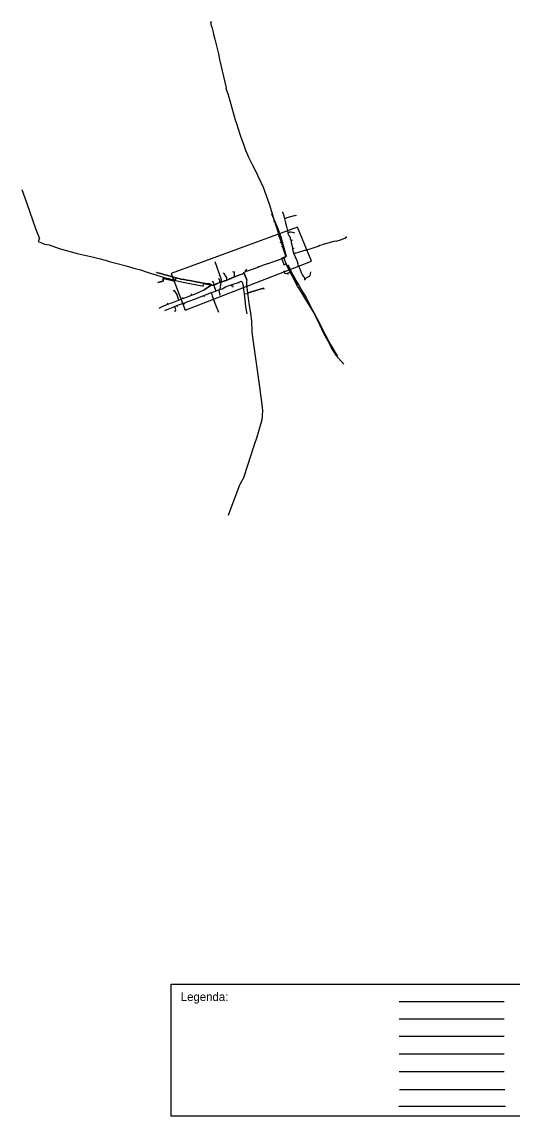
# Model space of a CAD drawing. Extents: x -703329 to -700959, y -1023502 to -1021532.
# Drawn here: x -703329 to -702465, y -1023458 to -1021532 of the extents above; entities that cross this region are included whole.
import ezdxf

# ---------------------------------------------------------------- set-up
doc = ezdxf.new("R2010")
doc.units = 0
for name, color, linetype in [('Vrstva 1', 7, 'Continuous'), ('Vrstva 2', 7, 'Continuous'), ('Vrstva 4', 7, 'Continuous'), ('Vrstva 63', 7, 'Continuous')]:
    doc.layers.add(name, color=color, linetype=linetype)

msp = doc.modelspace()

# ---------------------------------------------------------------- linework, layer by layer
at = {"layer": 'Vrstva 1'}
for p, q in [((-702664.172464, -1023255.776886), (-702478.762828, -1023255.776886)), ((-702664.172464, -1023286.503889), (-702478.762828, -1023286.503889)), ((-702664.172464, -1023317.230892), (-702478.762828, -1023317.230892)), ((-702664.172464, -1023347.957894), (-702478.762828, -1023347.957894)), ((-702664.172464, -1023379.35302), (-702478.762828, -1023379.35302)), ((-702663.25266, -1023410.831495), (-702477.843025, -1023410.831495)), ((-702664.422703, -1023440.270888), (-702476.414852, -1023440.270888))]:
    msp.add_line(p, q, dxfattribs=at)
for points in [[(-703328.627, -1021827.093), (-703320.441, -1021849.961), (-703303.784, -1021897.106), (-703297.781, -1021912.82), (-703298.038, -1021913.443), (-703299.559, -1021917.143), (-703300.128, -1021918.527), (-703293.861, -1021920.979), (-703288.734, -1021923.253), (-703280.419, -1021924.122), (-703262.932, -1021930.461), (-703231.327, -1021939.317), (-703217.484, -1021942.7), (-703204.749, -1021945.514), (-703190.729, -1021948.878), (-703178.041, -1021952.517), (-703172.493, -1021954.057), (-703163.326, -1021956.477), (-703145.017, -1021961.356), (-703131.4, -1021965.203), (-703119.891, -1021968.321), (-703107.62, -1021972.273), (-703083.486, -1021979.941), (-703077.893, -1021981.448), (-703070.423, -1021983.514), (-703057.214, -1021987.099), (-703044.292, -1021990.048), (-703032.48, -1021992.498), (-703020.324, -1021994.812), (-703011.714, -1021996.489)], [(-702889.616, -1021864.148), (-702887.85, -1021869.34), (-702886.67, -1021873.56), (-702883.87, -1021881.93), (-702883.51, -1021882.8)], [(-702869.594, -1021866.237), (-702869.46, -1021866.94), (-702867.93, -1021870.72), (-702865.76, -1021878.41)], [(-702867.93, -1021870.72), (-702865.76, -1021878.41)], [(-702865.76, -1021878.41), (-702864.035, -1021876.989), (-702857.367, -1021874.767), (-702845.672, -1021871.95), (-702845.402, -1021872.92)], [(-702865.76, -1021878.41), (-702864.05, -1021885.73)], [(-702884.788, -1021883.229), (-702883.51, -1021882.8)], [(-702883.51, -1021882.8), (-702881.58, -1021889.28), (-702879.86, -1021891.99), (-702879.44, -1021894.19), (-702878.88, -1021894.84), (-702875.17, -1021909.07)], [(-702864.05, -1021885.73), (-702862.52, -1021892.07), (-702861.44, -1021896.39), (-702860.84, -1021899.05), (-702859.81, -1021903.45)], [(-702862.52, -1021892.07), (-702861.44, -1021896.39)], [(-702876.092, -1021909.185), (-702875.17, -1021909.07)], [(-702875.17, -1021909.07), (-702873.9, -1021912.79), (-702872.05, -1021918.22), (-702871.51, -1021919.79), (-702870.54, -1021922.95), (-702869.2, -1021926.63)], [(-702873.9, -1021912.79), (-702872.05, -1021918.22)], [(-702860.84, -1021899.05), (-702859.81, -1021903.45)], [(-702859.81, -1021903.45), (-702857.14, -1021901.17), (-702855.53, -1021901.27), (-702851.63, -1021901.86), (-702848.458, -1021903.244)], [(-702859.81, -1021903.45), (-702859.23, -1021905.91), (-702857.45, -1021907.91), (-702856.11, -1021911.76), (-702855.91, -1021912.88), (-702854.81, -1021915.89), (-702854.698, -1021916.268)], [(-702855.91, -1021912.88), (-702854.81, -1021915.89)], [(-702854.698, -1021916.268), (-702852.809, -1021915.714), (-702851.882, -1021916.067)], [(-702854.698, -1021916.268), (-702854.12, -1021918.22), (-702854.05, -1021920.37), (-702852.12, -1021928.93), (-702851.89, -1021930.35), (-702851.833, -1021930.771)], [(-702847.95, -1021938.38), (-702846.71, -1021938.87), (-702845.83, -1021938.78), (-702842.95, -1021937.97), (-702830.28, -1021933.63), (-702828.21, -1021933.32), (-702816.91, -1021929.8), (-702806.89, -1021926.56), (-702803.66, -1021925.01), (-702798.55, -1021923.45), (-702797.52, -1021922.81), (-702795.07, -1021922.53), (-702776.56, -1021916.99), (-702774.96, -1021917.56), (-702767.18, -1021915.43), (-702759.63, -1021912.62), (-702756.7, -1021910.71), (-702756.48, -1021910.63), (-702756.757, -1021909.7)], [(-702912.33, -1021963.25), (-702911.91, -1021963.18), (-702902.23, -1021959.63), (-702898.93, -1021958.48), (-702897.04, -1021957.85), (-702895.96, -1021957.02), (-702894.48, -1021956.96), (-702878, -1021951.21), (-702864.71, -1021946.48), (-702863.57, -1021944.43), (-702866.29, -1021935.52)], [(-702871.51, -1021919.79), (-702870.54, -1021922.95)], [(-702870.509, -1021927.043), (-702869.2, -1021926.63)], [(-702866.29, -1021935.52), (-702867.17, -1021933.46), (-702868.09, -1021930.25), (-702869.2, -1021926.63)], [(-702868.09, -1021930.25), (-702867.17, -1021933.46)], [(-702851.833, -1021930.771), (-702848.639, -1021929.836)], [(-702851.833, -1021930.771), (-702851.6, -1021932.5), (-702850.04, -1021938.06)], [(-702850.04, -1021938.06), (-702849.52, -1021940.34), (-702845.04, -1021950.46), (-702844.19, -1021952.06), (-702842.4, -1021956.31), (-702843.26, -1021958.53), (-702842.59, -1021960.15), (-702841.93, -1021960.76)], [(-702850.04, -1021938.06), (-702847.95, -1021938.38)], [(-702849.52, -1021940.34), (-702845.04, -1021950.46)], [(-703090.69, -1021972.86), (-703090.44, -1021971.93)], [(-703076.98, -1021976.95), (-703084.06, -1021974.89), (-703089.77, -1021973.23), (-703090.69, -1021972.86)], [(-703090.69, -1021972.86), (-703089.77, -1021973.23), (-703084.06, -1021974.89), (-703076.98, -1021976.95)], [(-702973.715, -1021973.823), (-702972.591, -1021973.404), (-702970.446, -1021978.581), (-702968.39, -1021981.65), (-702968.23, -1021986.31)], [(-702948.291, -1021978.321), (-702937.184, -1021974.246), (-702936.546, -1021975.842), (-702932.464, -1021986.056), (-702933.07, -1021988.955), (-702932.663, -1021994.753), (-702928.736, -1022027.563), (-702925.495, -1022047.954), (-702924.396, -1022054.867), (-702924.106, -1022056.693), (-702923.266, -1022078.142), (-702916.795, -1022124.218), (-702910.182, -1022174.299), (-702905.394, -1022210.194), (-702904.438, -1022216.613), (-702906.141, -1022231.995), (-702914.848, -1022262.842), (-702919.275, -1022276.127), (-702920.535, -1022280.161), (-702921.603, -1022283.279), (-702925.395, -1022294.352), (-702937.779, -1022332.503), (-702938.28, -1022334.101), (-702938.76, -1022335.369), (-702943.944, -1022344.666), (-702945.34, -1022347.169), (-702960.655, -1022387.911), (-702965.12, -1022400.867)], [(-702956.654, -1021971.555), (-702955.577, -1021971.153), (-702954.761, -1021973.196), (-702954.77, -1021976.35), (-702954.69, -1021978.46), (-702955.23, -1021980.78)], [(-702955.23, -1021980.78), (-702949.74, -1021978.62), (-702945.56, -1021976.96), (-702939.41, -1021974.98), (-702937.64, -1021973.66), (-702937.4, -1021972.45), (-702937.34, -1021972.17), (-702935.43, -1021971.59), (-702934.122, -1021971.079)], [(-702934.122, -1021971.079), (-702935.43, -1021971.59)], [(-702934.122, -1021971.079), (-702934.759, -1021969.451), (-702932.537, -1021967.058)], [(-702934.122, -1021971.079), (-702932.82, -1021970.57), (-702925.85, -1021968.07), (-702922.57, -1021966.97), (-702920.52, -1021966.23), (-702912.33, -1021963.25)], [(-702932.82, -1021970.57), (-702934.122, -1021971.079)], [(-702922.57, -1021966.97), (-702920.52, -1021966.23)], [(-702912.94, -1021961.69), (-702912.33, -1021963.25)], [(-702902.23, -1021959.63), (-702898.93, -1021958.48)], [(-702867.452, -1021970.064), (-702866.729, -1021972.014), (-702865.69, -1021974.2), (-702864.11, -1021974.47), (-702860.69, -1021974.07)], [(-702860.69, -1021974.07), (-702855.76, -1021972.12)], [(-702860.69, -1021974.07), (-702860.309, -1021976.568)], [(-702855.76, -1021972.12), (-702845.19, -1021992.54), (-702843.24, -1021995.4)], [(-702841.93, -1021960.76), (-702841.17, -1021960.65)], [(-702841.93, -1021960.76), (-702840.2, -1021964.06)], [(-702841.93, -1021960.76), (-702840.2, -1021964.06), (-702838.47, -1021967.83), (-702836.52, -1021972.81), (-702834.07, -1021977.71), (-702832.79, -1021979.12), (-702831.51, -1021981.3), (-702830.44, -1021984.37)], [(-702830.44, -1021984.37), (-702828.95, -1021983.39), (-702827.84, -1021982.37), (-702820.822, -1021978.535), (-702819.657, -1021971.569)], [(-703079.52, -1021983.09), (-703079.39, -1021988.13), (-703086.78, -1021989.85), (-703089.16, -1021990.71)], [(-703057.096, -1021982.303), (-703057.44, -1021983.57), (-703059.04, -1021986.63), (-703059.58, -1021987.88), (-703060.14, -1021988.12), (-703062.99, -1021987.22), (-703076.5, -1021983.85), (-703079.52, -1021983.09)], [(-703076.98, -1021976.95), (-703076.68, -1021976.09)], [(-703065.426, -1021980.075), (-703071.31, -1021978.38), (-703076.98, -1021976.95)], [(-703076.98, -1021976.95), (-703071.31, -1021978.38), (-703065.426, -1021980.075)], [(-703065.426, -1021980.075), (-703065.256, -1021979.484)], [(-703057.096, -1021982.303), (-703059.12, -1021981.8), (-703062.98, -1021980.78), (-703065.426, -1021980.075)], [(-703065.426, -1021980.075), (-703062.98, -1021980.78), (-703059.12, -1021981.8), (-703057.096, -1021982.303)], [(-703062.99, -1021987.22), (-703060.14, -1021988.12), (-703059.58, -1021987.88), (-703059.04, -1021986.63), (-703057.44, -1021983.57), (-703057.096, -1021982.303)], [(-703056.829, -1021982.399), (-703057.096, -1021982.303)], [(-703057.096, -1021982.303), (-703056.829, -1021982.399)], [(-703056.829, -1021982.399), (-703056.79, -1021982.248)], [(-703054.854, -1021982.954), (-703056.829, -1021982.399)], [(-703056.829, -1021982.399), (-703054.854, -1021982.954)], [(-703049.595, -1021984.29), (-703054.854, -1021982.954)], [(-703054.854, -1021982.954), (-703049.595, -1021984.29)], [(-703049.595, -1021984.29), (-703049.374, -1021983.441)], [(-703039.37, -1021986.033), (-703043.42, -1021985.354), (-703049.14, -1021984.41), (-703049.595, -1021984.29)], [(-703049.595, -1021984.29), (-703049.14, -1021984.41), (-703043.42, -1021985.354), (-703039.37, -1021986.033)], [(-703039.37, -1021986.033), (-703039.243, -1021985.282)], [(-703029.535, -1021987.861), (-703033.112, -1021987.238), (-703038.382, -1021986.211), (-703039.37, -1021986.033)], [(-703039.37, -1021986.033), (-703038.382, -1021986.211), (-703033.112, -1021987.238), (-703029.535, -1021987.861)], [(-703029.57, -1022012.86), (-703021.4, -1022009.59), (-703007.3, -1022003.38), (-702995.36, -1021994.95), (-702993.48, -1021995.03)], [(-703029.535, -1021987.861), (-703029.404, -1021987.051)], [(-703029.535, -1021987.861), (-703024.682, -1021988.666), (-703020.708, -1021989.357), (-703015.28, -1021990.357)], [(-703015.28, -1021990.357), (-703020.708, -1021989.357), (-703024.682, -1021988.666), (-703029.535, -1021987.861)], [(-703015.28, -1021990.357), (-703015.138, -1021989.621)], [(-703015.28, -1021990.357), (-703012.37, -1021990.921), (-703008.422, -1021991.691), (-703001.49, -1021992.96), (-702997.57, -1021992.81), (-702993.48, -1021995.03)], [(-702993.48, -1021995.03), (-702997.57, -1021992.81), (-703001.49, -1021992.96), (-703008.422, -1021991.691), (-703012.37, -1021990.921), (-703015.28, -1021990.357)], [(-703011.027, -1021996.623), (-703009.263, -1021996.966), (-703007.79, -1021992.364), (-703006.323, -1021992.638)], [(-702995.36, -1021994.95), (-703007.3, -1022003.38)], [(-703006.323, -1021992.638), (-703005.537, -1021992.785)], [(-703005.537, -1021992.785), (-702996.942, -1021994.391), (-702991.596, -1021995.211), (-702986.613, -1021993.062)], [(-702993.48, -1021995.03), (-702992.91, -1021995.16), (-702992.34, -1021994.96)], [(-702993.28, -1021987.888), (-702991.46, -1021990.58), (-702990.34, -1021994.97)], [(-702992.34, -1021994.96), (-702990.71, -1021995.01)], [(-702990.71, -1021995.01), (-702990.34, -1021994.97)], [(-702990.34, -1021994.97), (-702987.613, -1021993.592), (-702986.84, -1021993.19), (-702983.98, -1021991.88), (-702980.542, -1021990.57)], [(-702990.34, -1021994.97), (-702987.613, -1021993.592), (-702986.84, -1021993.19)], [(-702986.613, -1021993.062), (-702985.408, -1021992.543), (-702980.036, -1021990.512), (-702974.43, -1021988.604), (-702968.893, -1021986.753), (-702960.411, -1021983.749), (-702955.208, -1021981.166), (-702952.324, -1021979.801)], [(-702982.458, -1021984.104), (-702981.476, -1021983.733), (-702980.473, -1021986.39), (-702980.542, -1021990.57)], [(-702980.542, -1021990.57), (-702976.39, -1021988.99), (-702973.16, -1021987.99), (-702970.83, -1021987.17)], [(-702970.83, -1021987.17), (-702968.23, -1021986.31)], [(-702968.23, -1021986.31), (-702966.33, -1021985.61), (-702962.95, -1021984.1), (-702962.62, -1021983.76)], [(-702968.23, -1021986.31), (-702966.33, -1021985.61), (-702962.95, -1021984.1)], [(-702963.51, -1021996.08), (-702960.12, -1021994.67)], [(-702962.62, -1021983.76), (-702961.796, -1021983.428)], [(-702961.796, -1021983.428), (-702955.23, -1021980.78)], [(-702961.796, -1021983.428), (-702961.19, -1021984.93)], [(-702960.12, -1021994.67), (-702956.07, -1021993.54), (-702947.22, -1021990.29)], [(-702960.12, -1021994.67), (-702959.45, -1021996.32), (-702957.791, -1021995.709), (-702956.725, -1021998.591)], [(-702955.23, -1021980.78), (-702949.74, -1021978.62)], [(-702952.324, -1021979.801), (-702948.291, -1021978.321)], [(-702947.22, -1021990.29), (-702942, -1021988.35), (-702941.13, -1021989.14), (-702940.77, -1021990.19), (-702939.01, -1021995.89), (-702938.86, -1021997.73), (-702937.98, -1022003.39), (-702937.059, -1022010.427)], [(-702947.22, -1021990.29), (-702946.716, -1021991.562)], [(-702932.464, -1021986.056), (-702936.546, -1021975.842)], [(-702831.51, -1021981.3), (-702830.44, -1021984.37)], [(-702830.44, -1021984.37), (-702829.22, -1021986.54)], [(-703062.355, -1022004.654), (-703060.038, -1022004.594), (-703058.796, -1022007.739), (-703055.86, -1022011.516), (-703055.571, -1022012.315), (-703054.293, -1022016), (-703052.6, -1022020.94), (-703052.53, -1022021.64)], [(-703045.07, -1022018.9), (-703036.63, -1022015.53), (-703029.57, -1022012.86)], [(-703043.294, -1022026.675), (-703039.68, -1022025.52), (-703036.28, -1022023.76), (-703022.66, -1022019.03), (-703009.66, -1022013.84), (-703006.964, -1022012.752)], [(-703030.576, -1022010.701), (-703029.57, -1022012.86)], [(-703011.714, -1021996.489), (-703011.027, -1021996.623)], [(-703007.387, -1022015.356), (-703007.623, -1022014.461), (-703006.459, -1022014.005), (-703006.964, -1022012.752)], [(-703006.964, -1022012.752), (-703003.59, -1022011.39), (-702994.97, -1022008.06)], [(-702994.97, -1022008.06), (-702987.2, -1022005.48)], [(-702994.97, -1022008.06), (-702994.46, -1022009.57), (-702993.59, -1022013.95), (-702990.69, -1022021.95), (-702987.43, -1022029.77), (-702982.014, -1022042.747)], [(-702990.71, -1021995.01), (-702990.05, -1021997.78), (-702987.65, -1022003.98), (-702987.2, -1022005.48)], [(-702990.05, -1021997.78), (-702987.65, -1022003.98)], [(-702987.2, -1022005.48), (-702985.42, -1022004.86), (-702982.23, -1022003.71)], [(-702982.23, -1022003.71), (-702980.06, -1022002.73), (-702978.15, -1022002.27), (-702977.412, -1022002.03)], [(-702982.23, -1022003.71), (-702981.84, -1022004.85), (-702979.648, -1022012.612), (-702980.584, -1022012.964)], [(-702977.61, -1022001.42), (-702977.412, -1022002.03)], [(-702977.412, -1022002.03), (-702975.57, -1022001.43)], [(-702975.57, -1022001.43), (-702970.09, -1021998.26), (-702963.51, -1021996.08)], [(-702938.86, -1021997.73), (-702937.98, -1022003.39)], [(-702937.059, -1022010.427), (-702935.693, -1022010.271), (-702931.202, -1022009.757), (-702929.635, -1022009.578)], [(-702937.059, -1022010.427), (-702935.7, -1022020.81), (-702934.36, -1022033.51), (-702932.55, -1022045.5)], [(-702935.693, -1022010.271), (-702931.202, -1022009.757)], [(-702902.341, -1022002.418), (-702903.167, -1022000.265), (-702929.719, -1022008.771), (-702929.635, -1022009.578)], [(-702929.635, -1022009.578), (-702929.719, -1022008.771), (-702903.167, -1022000.265), (-702902.341, -1022002.418)], [(-703086.51, -1022035.8), (-703081.39, -1022033.01), (-703071.41, -1022028.85)], [(-703076.69, -1022039.84), (-703069.62, -1022036.78), (-703063.92, -1022034.68), (-703059.22, -1022032.75)], [(-703072.358, -1022026.159), (-703071.41, -1022028.85)], [(-703071.41, -1022028.85), (-703061.38, -1022025.05), (-703052.53, -1022021.64)], [(-703059.486, -1022041.225), (-703057.68, -1022040.41), (-703057.58, -1022038.66), (-703058.69, -1022034.31), (-703059.22, -1022032.75)], [(-703059.22, -1022032.75), (-703055.59, -1022030.96)], [(-703055.59, -1022030.96), (-703049.31, -1022028.51), (-703045.87, -1022027.5), (-703044.68, -1022027.16), (-703043.294, -1022026.675)], [(-703055.59, -1022030.96), (-703054.912, -1022032.878)], [(-703052.53, -1022021.64), (-703045.07, -1022018.9)], [(-703045.918, -1022016.521), (-703045.07, -1022018.9)], [(-703043.294, -1022026.675), (-703042.724, -1022028.127), (-703042.469, -1022028.779), (-703042.655, -1022028.852)]]:
    msp.add_lwpolyline(points, dxfattribs=at)
msp.add_lwpolyline([(-703065.72, -1023225.730735), (-701845.700224, -1023225.730735), (-701845.700224, -1023457.8), (-703065.72, -1023457.8)], close=True, dxfattribs=at)
at = {"layer": 'Vrstva 2'}
for points in [[(-702994.702, -1021531.797), (-702996.44, -1021532.265), (-702994.903, -1021537.991), (-702993.551, -1021543.128), (-702992.341, -1021547.724), (-702990.852, -1021553.381), (-702988.568, -1021562.424), (-702982.486, -1021588.197), (-702980.282, -1021598.185), (-702978.079, -1021607.997), (-702968.564, -1021647.601), (-702968.51, -1021647.93), (-702968.646, -1021648.285), (-702969.029, -1021648.722), (-702967.556, -1021653.484), (-702966.46, -1021657.358), (-702966.023, -1021657.385), (-702965.687, -1021657.681), (-702962.463, -1021670.607), (-702960.653, -1021676.887), (-702952.708, -1021704.448), (-702950.532, -1021710.762), (-702944.414, -1021729.684), (-702942.636, -1021734.832), (-702938.285, -1021747.08), (-702936.188, -1021752.385), (-702934.346, -1021757.369), (-702932.143, -1021762.999), (-702929.78, -1021768.769), (-702927.126, -1021774.546), (-702922.233, -1021784.112), (-702918.888, -1021790.249), (-702903.575, -1021822.738), (-702892.6, -1021853.752), (-702889.337, -1021863.869), (-702885.192, -1021877.259), (-702879.207, -1021895.257), (-702875.339, -1021908.573)], [(-702888.769, -1021869.757), (-702877.903, -1021895.581), (-702872.054, -1021911.93)], [(-702876.39, -1021908.899), (-702875.339, -1021908.573)], [(-702875.339, -1021908.573), (-702873.863, -1021912.512), (-702871.54, -1021919.442)], [(-702872.054, -1021911.93), (-702869.926, -1021918.91), (-702862.751, -1021944.027), (-702862.513, -1021944.556), (-702863.863, -1021944.968)], [(-702873.553, -1021920.105), (-702871.54, -1021919.442)], [(-702871.54, -1021919.442), (-702863.322, -1021944.211), (-702863.551, -1021944.63), (-702863.863, -1021944.968)], [(-702866.123, -1021945.979), (-702870.757, -1021947.857), (-702870.418, -1021948.893), (-702867.132, -1021958.955), (-702867.017, -1021959.307), (-702864.129, -1021958.297), (-702861.396, -1021961.736), (-702858.756, -1021966.775), (-702855.194, -1021973.885), (-702850.893, -1021982.188), (-702845.783, -1021991.988), (-702845.445, -1021992.789), (-702844.139, -1021995.883), (-702843.789, -1021996.713), (-702840.842, -1022001.186), (-702834, -1022011.699), (-702829.935, -1022018.592), (-702823.966, -1022028.331), (-702817.827, -1022038.394), (-702814.883, -1022043.496), (-702804.173, -1022064.736), (-702800.883, -1022072.28), (-702797.84, -1022078.427), (-702792.2, -1022088.796), (-702789.696, -1022093.411), (-702783.89, -1022104.49), (-702783.414, -1022105.305), (-702775.35, -1022118.162), (-702761.566, -1022134.511)], [(-702866.123, -1021945.979), (-702867.024, -1021947.013), (-702866.874, -1021947.467), (-702863.259, -1021958.384), (-702862.74, -1021959.95), (-702860.323, -1021961.198), (-702858.872, -1021962.041), (-702858.443, -1021962.492)], [(-702866.123, -1021945.979), (-702864.466, -1021945.152), (-702863.863, -1021944.968)], [(-702866.123, -1021945.979), (-702864.536, -1021945.336), (-702863.939, -1021945.05), (-702863.863, -1021944.968)], [(-702859.457, -1021959.606), (-702859.898, -1021959.756), (-702858.443, -1021962.492)], [(-702858.443, -1021962.492), (-702853.423, -1021972.956), (-702848.677, -1021981.032), (-702843.389, -1021990.739), (-702840.414, -1021994.959), (-702831.606, -1022010.247), (-702827.541, -1022017.14), (-702817.141, -1022037.982), (-702814.454, -1022043.238), (-702803.348, -1022064.376), (-702799.783, -1022071.801), (-702788.489, -1022092.926), (-702785.6, -1022098.235), (-702782.594, -1022103.96), (-702772.673, -1022120.549)], [(-703089.16, -1021990.71), (-703086.78, -1021989.85), (-703079.39, -1021988.13), (-703079.52, -1021983.09), (-703076.5, -1021983.85), (-703062.99, -1021987.22)]]:
    msp.add_lwpolyline(points, dxfattribs=at)
at = {"layer": 'Vrstva 4'}
msp.add_lwpolyline([(-702979.154, -1022002.148), (-702976.888, -1021985.92), (-702987.984, -1021954.093)], dxfattribs=at)
at = {"layer": 'Vrstva 63'}
msp.add_lwpolyline([(-703065.72, -1021974.52), (-703041.08, -1022039.48), (-702818.2, -1021953.24), (-702842.84, -1021893.32), (-703065.72, -1021974.52)], close=True, dxfattribs=at)

# ---------------------------------------------------------------- texts
at = {"layer": 'Vrstva 1'}
msp.add_text('Legenda:', height=15, dxfattribs=at).set_placement((-703048.563, -1023255.213735))

doc.saveas('drawing.dxf')
